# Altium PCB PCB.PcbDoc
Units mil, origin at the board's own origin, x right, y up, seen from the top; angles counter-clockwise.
Board outline 3815.03 x 1595.03 mil, 2 copper layers (Top Layer, Bottom Layer); 34 components, 24 nets, 91 pads, 348 vias.
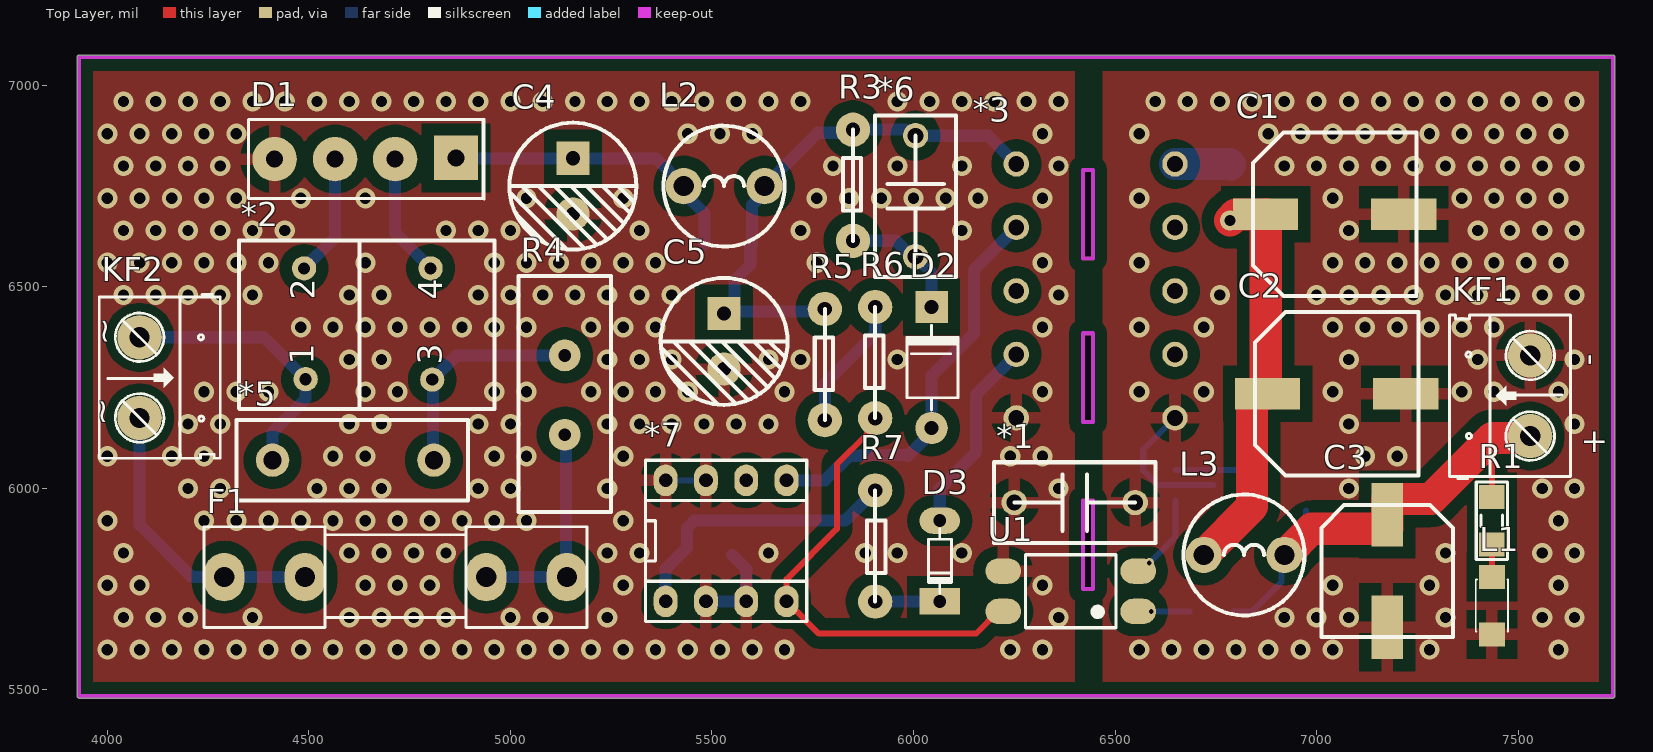
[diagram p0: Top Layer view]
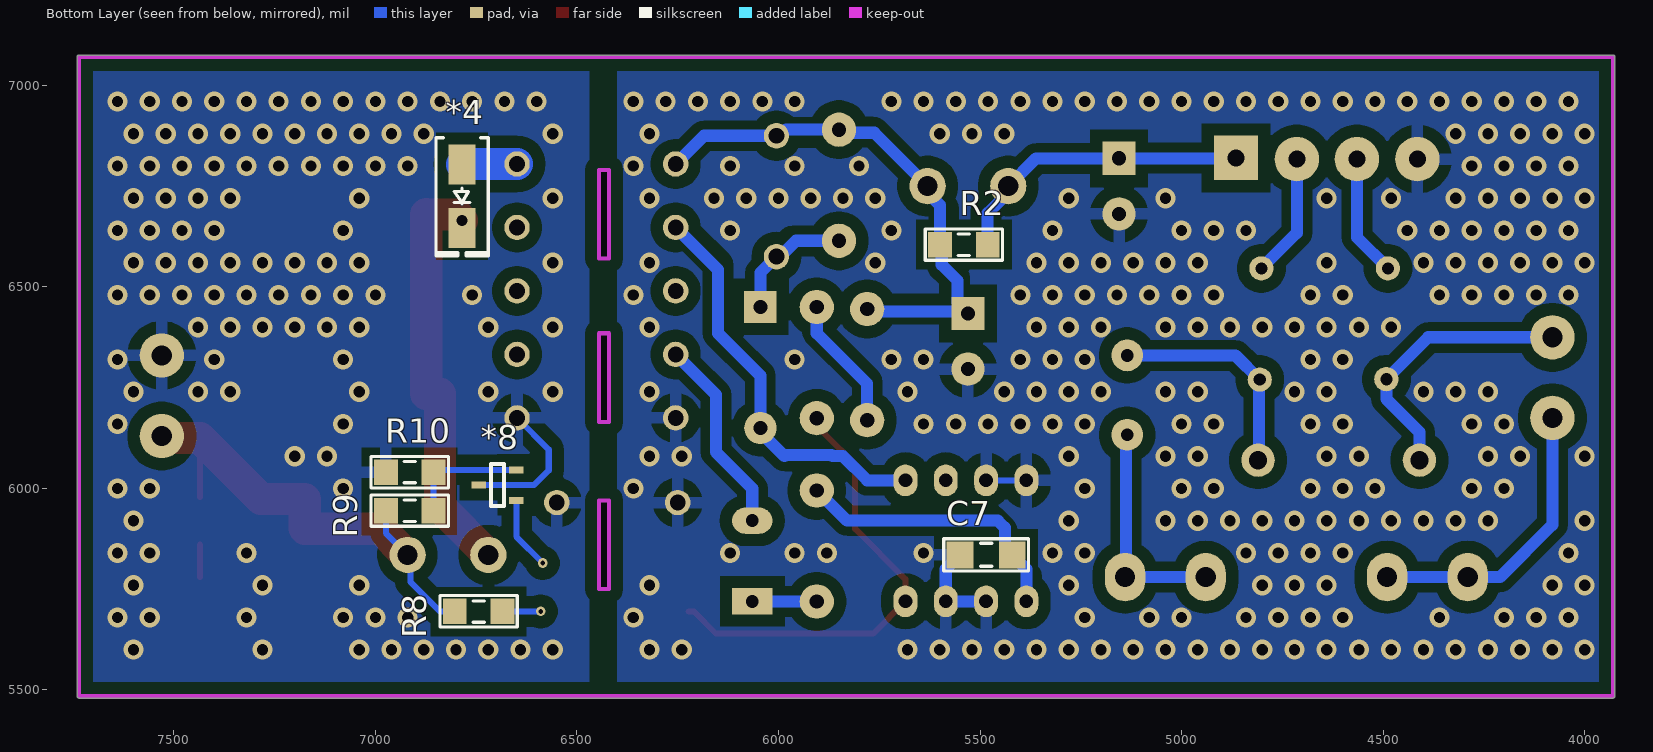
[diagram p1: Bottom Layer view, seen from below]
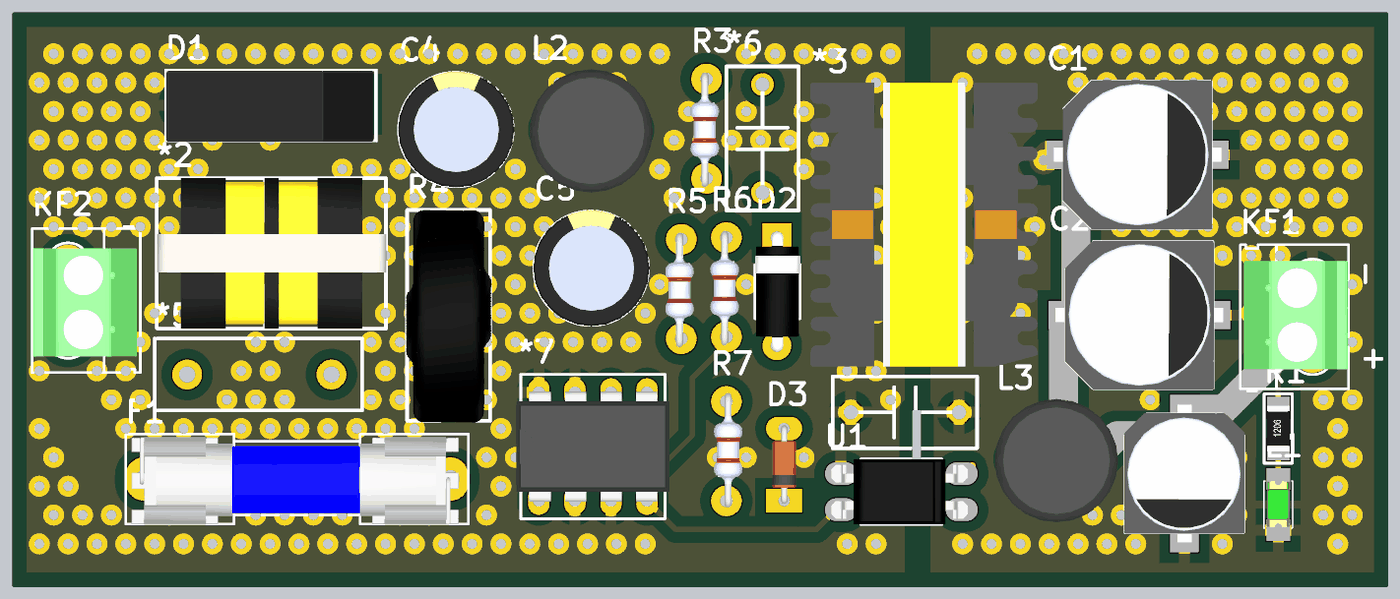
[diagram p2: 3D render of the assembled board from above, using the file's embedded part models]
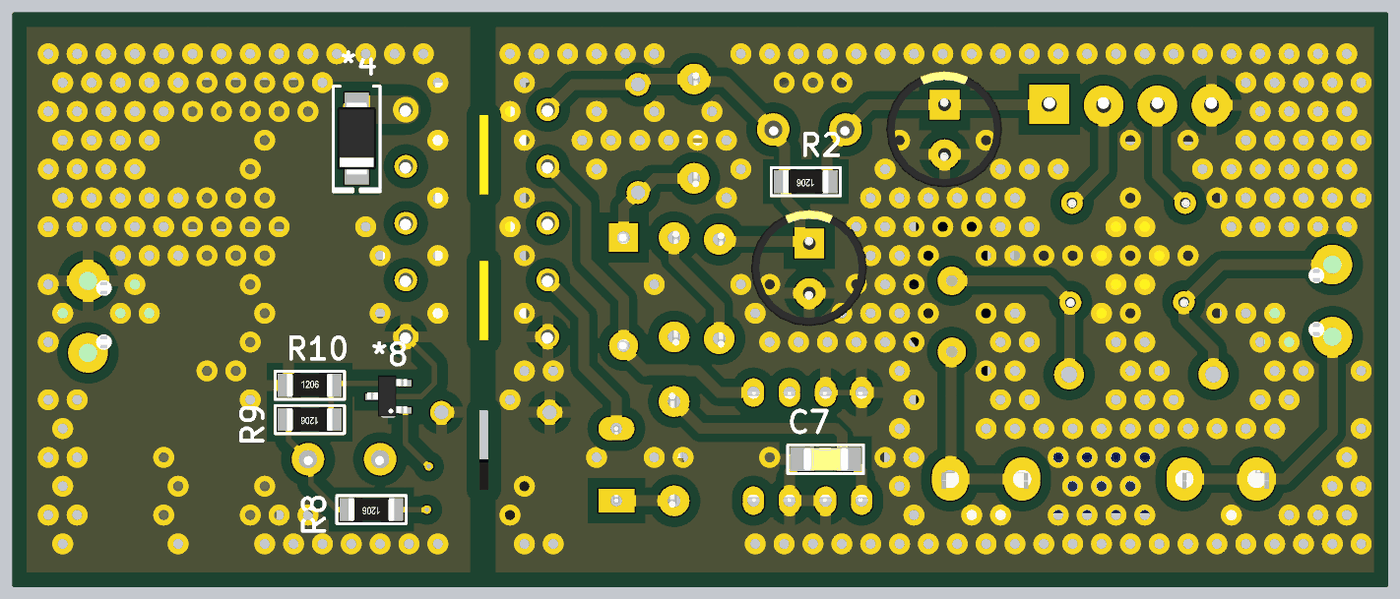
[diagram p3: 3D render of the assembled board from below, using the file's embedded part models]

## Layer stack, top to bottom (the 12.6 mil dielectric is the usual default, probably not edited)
Top Solder: solder mask 0.4, Solder Resist, Dk 3.5
Top Layer: signal copper 1.4
Dielectric 1: dielectric 12.6, FR-4, Dk 4.8
Bottom Layer: signal copper 1.4
Bottom Solder: solder mask 0.4, Solder Resist, Dk 3.5

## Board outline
3930,5479.98 cw(c3930,5485) 3924.99,5485 3924.99,7070 cw(c3930,7070) 3930,7075.02 7735,7075.02 cw(c7735,7070) 7740.02,7070 7740.02,5485 cw(c7735,5485) 7735,5479.98
cut-out: 6420,6570 6420,6790 6445,6790 6445,6570
cut-out: 6420,6165 6445,6165 6445,6385 6420,6385
cut-out: 6420,5750 6445,5750 6445,5970 6420,5970

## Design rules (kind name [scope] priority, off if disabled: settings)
Clearance [All] p1: gap=30 ignorepadtopadclearanceinfootprint=FALSE
PlaneClearance [All] p1: clearance=30
PlaneConnect [All] p1: planeconnectstyle=Relief reliefexpansion=30 reliefentries=4 reliefconductorwidth=30 reliefairgap=10
PolygonConnect [All] p1: connectstyle=Relief reliefconductorwidth=30 reliefentries=4 polygonreliefangle="90 Angle" airgapwidth=30
RoomDefinition SCH [InComponentClass('SCH')] p1: confinementstyle=ConfineIn formatcopy=TRUE lockcomponents=FALSE outline 0,0 2000,0 2000,1000 0,1000
RoutingVias [All] p1: holewidth=28 width=50 viastyle="Through Hole" minholewidth=28 minwidth=50 maxholewidth=28 maxwidth=50
SolderMaskExpansion [All] p1: expansion=4 istentingtop=FALSE
Width [All] p1: maxlimit=80 minlimit=15 preferedwidth=30
28 further rules are at their usual default settings.

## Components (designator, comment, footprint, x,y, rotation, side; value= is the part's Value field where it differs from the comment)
*1 "Tu cao ap 101/1000V" "Tu cao ap" 6650,5865 r180 top
*2 "INDUCTOR UU9.8" "INDUCTOR UU9.8" 4605,6330 r90 top
*3 "Transformer EE22" "TRANSFORMER EE22" 6908.54,6407.32 r0 top
*4 "Diode SS54 (1N5824)" "DIODE SMA" 6785,6725 r270 bottom
*5 "Tu keo vang 0.1uF" "Tu keo vang 0.1uF" 4920,6020 r0 top
*6 "Tu cao ap 2.2nF 1KV" "Tu cao ap" 6105,6975 r270 top
*7 "TNY266" DIP8 5535,5870 r0 top
*8 "TL431" "TL431 SOT-23-3" 6640,5985 r0 bottom
C1 "1000uF" "tu nhom 10 (G)" 7045,6680 r0 top
C2 "1000uF" "tu nhom 10 (G)" 7050,6235 r0 top
C3 "470uF" "tu nhom 8 (f)" 7175,5795.24 r270 top
C4 "4.7uF/400V" "tu hoa 8mm" 5155,6750 r270 top
C5 "4.7uF/400V" "tu hoa 8mm" 5530,6365 r270 top
C7 "104" "tu 1206" 5485,5835 r180 bottom
D1 "2A 600V" "DIODE CAU 2A 3A CAM" 4865,6818 r180 top
D2 "1N4973" "DIODE 1A" 6045,6100 r270 top
D3 "1N4148" "DIODE 0.5A" 6065,5820 r90 top
F1 "2A" "De Cau Chi 520 630" 4715,5780 r180 top
KF1 "5V/3A" "Con 2 KF301 5.08" 7530,6130 r90 top
KF2 "AC in" "Con 2 KF301 5.08" 4080,6375 r270 top
L1 "LED 0805" LED-1206-Green 7435,5780 r270 top
L2 "2.2mH/3A" "CUON CAM 100uH3A" 5530,6750 r0 top
L3 "10uH - 3A" "CUON CAM 100uH3A" 6820,5835 r0 top
R1 "200R" "tro smd 1206" 7435,5920 r90 top
R2 "1.2k" "tro smd 1206" 5540,6605 r0 bottom
R3 "200K" "Dien tro" 5850,6614.41 r90 top
R4 "10D-9" "tro nhiet d-9" 5135,6231.57 r270 top
R5 "2M" "Dien tro" 5780,6169.41 r90 top
R6 "2M" "Dien tro" 5905,6174.41 r90 top
R7 "10K" "Dien tro" 5905,5995 r270 top
R8 "1k" "tro smd 1206" 6744.06,5695 r0 bottom
R9 "4.7k" "tro smd 1206" 6915,5945 r0 bottom
R10 "4.7k" "tro smd 1206" 6915,6040 r180 bottom
U1 "OPTO PC817 SMD" SOP4 6390,5745 r180 top value=PC817

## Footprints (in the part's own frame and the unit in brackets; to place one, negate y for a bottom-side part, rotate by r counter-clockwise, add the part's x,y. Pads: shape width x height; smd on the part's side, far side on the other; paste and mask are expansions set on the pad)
"Con 2 KF301 5.08" [mil]
  round 110 hole 50: 1(0,0) 2(200,0)
  silkscreen extent -106,-100 300,200, body extent -45,-97 255,190, height 335
"CUON CAM 100uH3A" [mil] "100uH3A"
  round 90 hole 50: 1(-100,0) 2(100,0)
  silkscreen extent -150,-150 150,150, body extent -171,-175 171,167, height 394
"De Cau Chi 520 630" [mil] "De Fuse"
  oval 100x120 hole 50: 1(-425,0) 1(-225,0) 2(225,0) 2(425,0)
  silkscreen extent -475,-125 475,125, body extent -448,-117 459,127, height 378
"Dien tro" [mm] "c?m"
  round 2.16 hole 0.9: 1(0,0) 2(7,0)
  silkscreen extent 0,-0.51 7,0.64, body extent -0.62,-0.87 7.48,1.13, height 2.5
"DIODE 0.5A" [mil] "Diode muoi, xung"
  oval 65x100 hole 32: 1(100,0)
  rect 65x100 hole 32: 2(-100,0)
  silkscreen extent -80,-30 80,28, body extent -108,-33 108,32, height 61
"DIODE 1A" [mil] "Diode 1A"
  round 80 hole 35: 1(-50,0)
  rect 80x80 hole 35: 2(-350,0)
  silkscreen extent -305,-61 -95,65, body extent -366,-61 -34,65, height 122
"DIODE CAU 2A 3A CAM" [mil] "DIODE CAU 2A 3A CAM"
  round 110 hole 42: 1(450,1) 2(300,1) 3(151,1)
  rect 110x110 hole 42: 4(0,-2)
  silkscreen extent -70,-97 515,100, body extent -62,-95 512,102, height 650
"DIODE SMA" [mm] "SMA"
  rect 2.5x1.7 smd: 1(-2,0) 2(2,0)
  silkscreen extent -3.68,-1.65 3.75,1.65, body extent -2.6,-1.37 2.6,1.37, height 2.4
DIP8 [mm] "W.300/L.400"
  oval 1.5x2 hole 0.864: 1(-3.81,-3.81) 2(-1.27,-3.81) 3(1.27,-3.81) 4(3.81,-3.81) 5(3.81,3.81) 6(1.27,3.81) 7(-1.27,3.81) 8(-3.81,3.81)
  silkscreen extent -5.08,-5.08 5.08,5.08, body extent -5.4,-3.88 5.4,3.88, height 4.5
"INDUCTOR UU9.8" [mil]
  round 60 hole 30: 1(-59,113) 2(216,117) 3(-60,-201) 4(216,-197)
  silkscreen extent -133,-356 285,279, body extent -132,-357 286,279, height 602
LED-1206-Green [mil]
  rect 60x65 smd: 1(0,0) 2(142,0)
  silkscreen extent 6,-40 136,40, body extent 7,-31 133,32, height 43
SOP4 [mm]
  oval 2.25x1.6 smd: 1(-4.25,1.27) 2(-4.25,-1.27) 3(4.25,-1.27) 4(4.25,1.27)
  silkscreen extent -2.85,-2.3 2.85,2.3, body extent -4.67,-2.29 4.93,2.31, height 3.6
"TL431 SOT-23-3" [mm]
  rect 0.9x0.44 smd: 1(0.264,0.373) 2(0.264,-1.547) 3(2.634,-0.587)
  silkscreen extent 1.05,-1.91 1.86,0.73, body extent 0.13,-2.09 2.93,0.81, height 1.3
"TRANSFORMER EE22" [mm]
  round 1.6 hole 1: 1(-16.6,10.1) 2(-16.6,6.1) 3(-16.6,2.1) 4(-16.6,-1.9) 5(-16.6,-5.9) 6(-6.6,-5.9) 7(-6.6,-1.9) 8(-6.6,2.1) 9(-6.6,6.1) 10(-6.6,10.1)
  body extent -19.6,-8.01 -3.57,12.01, height 20.81
"tro nhiet d-9" [mm]
  round 2 hole 0.8: 1(-2.5,0) 2(2.5,0)
  silkscreen extent -7.49,-2.92 7.37,2.92, body extent -7.5,-3 7.5,3, height 23.5
"tro smd 1206" [mm]
  rect 1.5x1.6 smd: 1(-1.5,0) 2(1.5,0)
  silkscreen extent -2.44,-0.99 2.44,0.99, body extent -1.6,-0.8 1.6,0.8, height 0.6
"tu 1206" [mm]
  rect 1.7x1.7 smd: 1(-1.65,0) 2(1.65,0)
  silkscreen extent -2.67,-1.02 2.67,1.02, body extent -1.57,-0.8 1.63,0.8, height 0.94
"Tu cao ap" [mm]
  round 1.6 hole 1: 1(2.54,-2.54) 2(10.16,-2.54)
  silkscreen extent 1.27,-5.08 11.43,0
"tu hoa 8mm" [mm]
  rect 2.1x2.1 hole 0.9: 1(-1.75,0)
  round 2.1 hole 0.9: 2(1.75,0)
  silkscreen extent -4,-4 4,4, body extent -4.1,-4.07 4.1,4.13, height 13.81
"Tu keo vang 0.1uF" [mil]
  round 82.68 hole 45: 1(-510,50) 2(-110,50)
  silkscreen extent -600,-50 -25,150
"tu nhom 8 (f)" [mm]
  rect 4x2 smd: 1(-3.55,0) 2(3.55,0)
  silkscreen extent -4.15,-4.15 4.15,4.15, body extent -4.85,-4.25 4.85,4.25, height 10.5
"tu nhom 10 (G)" [mm]
  rect 4.1x2 smd: 1(-4.35,0) 2(4.35,0)
  silkscreen extent -5.15,-5.15 5.15,5.15, body extent -5.9,-5.25 5.9,5.25, height 10.5

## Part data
*1: library part "Tu cao ap 1000V"
*7: library part TNY264
C1 C2: library part "Tu Nhom 1000uF 10V", "Dán"
C3: library part "Tu Nhom 470uF 16V", "Dán"
C4 C5: library part "Tu Hoa 4.7uF 400V 8x12", "Cắm"
C7: library part "Tu 1206 104 50V 20%", "Dán"
D1: library part "Diode CAU 2A VUONG", "Cắm"
D2: library part "Diode 1N4007", "Cắm"
D3: library part "Diode 1N4148", "Cắm"
F1: library part "De Cau Chi 520 630", "5x20mm"
KF1 KF2: library part "CON 2 KF301", "Cắm"
L1: library part "LED 1206 Xanh La", "Dán"
L2 L3: library part "CUON CAM 470uH DIP", "Cắm"
R1: library part "Tro 1206 1% 200R", "Dán"
R2 R8: library part "Tro 1206 1% 1k", "Dán"
R3 R5 R6 R7: library part Resistor, "Cắm"
R4: library part "Tro Nhiet NTC 10D-9", "Cắm"
R9 R10: library part "Tro 1206 5% 4.7K", "Dán"
U1: "Single Opto"

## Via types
v1: diameter 50, hole 28, Top Layer to Bottom Layer, 346 vias
v2: diameter 23.62, hole 11.81, Top Layer to Bottom Layer, 2 vias

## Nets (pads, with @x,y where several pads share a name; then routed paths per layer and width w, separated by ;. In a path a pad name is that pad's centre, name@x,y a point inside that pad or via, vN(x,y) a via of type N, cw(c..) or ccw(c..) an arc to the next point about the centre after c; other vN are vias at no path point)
Hi_groud: *1.2 *3.5 *7.2 *7.3 *7.7 *7.8 C4.2 C5.2 C7.1 D1.1 U1.3 | length 329.5
  Bottom Layer w15: *7.8 *7.7
  Bottom Layer w30: *7.2 *7.3 5585,5799.96 C7.1
  other v1: 4000,5600 4080,5600 4160,5600 4240,5600 4320,5600 4400,5600 4480,5600 4560,5600 4640,5600 4720,5600 4800,5600 4880,5600 4960,5600 5040,5600 5120,5600 5200,5600 5280,5600 5360,5600 5440,5600 5520,5600 5600,5600 5680,5600 6240,5600 6320,5600 4040,5680 4120,5680 4200,5680 4360,5680 4600,5680 4680,5680 4760,5680 4840,5680 5000,5680 5080,5680 5240,5680 6360,5680 4000,5760 4080,5760 4640,5760 4720,5760 4800,5760 5280,5760 6320,5760 4040,5840 4600,5840 4680,5840 4760,5840 4840,5840 5240,5840 5320,5840 5640,5840 5880,5840 5960,5840 6120,5840 4000,5920 4240,5920 4320,5920 4400,5920 4480,5920 4560,5920 4640,5920 4720,5920 4800,5920 4880,5920 4960,5920 5040,5920 5280,5920 4200,6000 4280,6000 4520,6000 4600,6000 4680,6000 4920,6000 5000,6000 5240,6000 6360,6000 4000,6080 4160,6080 4240,6080 4560,6080 4640,6080 4960,6080 5040,6080 5280,6080 6240,6080 6320,6080 4200,6160 4280,6160 4600,6160 4680,6160 4920,6160 5000,6160 5240,6160 5320,6160 5400,6160 5480,6160 5560,6160 5640,6160 4240,6240 4320,6240 4400,6240 4640,6240 4720,6240 4960,6240 5040,6240 5200,6240 5280,6240 5360,6240 5440,6240 5680,6240 6320,6240 4600,6320 4680,6320 5240,6320 5320,6320 5400,6320 5640,6320 5720,6320 5960,6320 4480,6400 4560,6400 4640,6400 4720,6400 4800,6400 4880,6400 4960,6400 5040,6400 5200,6400 5280,6400 5360,6400 6320,6400 4040,6480 4120,6480 4200,6480 4280,6480 4360,6480 4600,6480 4680,6480 4920,6480 5000,6480 5080,6480 5160,6480 5240,6480 5320,6480 5400,6480 6360,6480 4000,6560 4080,6560 4160,6560 4240,6560 4320,6560 4400,6560 4640,6560 4960,6560 5040,6560 5120,6560 5200,6560 5280,6560 5360,6560 5760,6560 6320,6560 4040,6640 4120,6640 4200,6640 4280,6640 4360,6640 4440,6640 4840,6640 4920,6640 5000,6640 5320,6640 5720,6640 6120,6640 4000,6720 4080,6720 4160,6720 4240,6720 4320,6720 4480,6720 4640,6720 5040,6720 5280,6720 5760,6720 5840,6720 5920,6720 6000,6720 6080,6720 6160,6720 6320,6720 4040,6800 4120,6800 4200,6800 4280,6800 5800,6800 5960,6800 6120,6800 6360,6800 4000,6880 4080,6880 4160,6880 4240,6880 4320,6880 5440,6880 5520,6880 5600,6880 6320,6880 4040,6960 4120,6960 4200,6960 4280,6960 4360,6960 4440,6960 4520,6960 4600,6960 4680,6960 4760,6960 4840,6960 4920,6960 5000,6960 5080,6960 5160,6960 5240,6960 5320,6960 5400,6960 5480,6960 5560,6960 5640,6960 5720,6960 5960,6960 6040,6960 6120,6960 6200,6960 6280,6960 6360,6960
Lo_gnd: *1.1 *3.6 *8.3 C1.2 C2.2 C3.2 KF1.2 L1.2 R10.1 | length 351.6
  Bottom Layer w15: *3.6 6570,6096.34 6570,6045 6606.88,6008.12 *8.3
  other v1: 6560,5600 6640,5600 6720,5600 6800,5600 6880,5600 6960,5600 7040,5600 7280,5600 7600,5600 6920,5680 7000,5680 7080,5680 7320,5680 7560,5680 7640,5680 7040,5760 7280,5760 7600,5760 7320,5840 7560,5840 7640,5840 7600,5920 7080,6000 7560,6000 7640,6000 7120,6080 7200,6080 7080,6160 7640,6160 6560,6240 6720,6240 7040,6240 7360,6240 7440,6240 7600,6240 7080,6320 7400,6320 7640,6320 6560,6400 6720,6400 7040,6400 7120,6400 7200,6400 7280,6400 7360,6400 7440,6400 6760,6480 7000,6480 7080,6480 7160,6480 7240,6480 7320,6480 7400,6480 7480,6480 7560,6480 7640,6480 6560,6560 7040,6560 7120,6560 7200,6560 7280,6560 7360,6560 7440,6560 7520,6560 7600,6560 7080,6640 7400,6640 7480,6640 7560,6640 7640,6640 6560,6720 7040,6720 7360,6720 7440,6720 7520,6720 7600,6720 6920,6800 7000,6800 7080,6800 7160,6800 7240,6800 7320,6800 7400,6800 7480,6800 7560,6800 7640,6800 6560,6880 6880,6880 6960,6880 7040,6880 7120,6880 7200,6880 7280,6880 7360,6880 7440,6880 7520,6880 7600,6880 6600,6960 6680,6960 6760,6960 6840,6960 6920,6960 7000,6960 7080,6960 7160,6960 7240,6960 7320,6960 7400,6960 7480,6960 7560,6960 7640,6960
Net*2_1: *2.1 *5.1 KF2.1 | length 697.1
  Bottom Layer w15: *5.1@4405,6070 4410,6075 *5.1
  Bottom Layer w30: KF2.1 4388,6375 *2.1 4492,6222 4410,6140 *5.1@4410,6075
Net*2_2: *2.2 D1.2 | length 302.9
  Bottom Layer w30: *2.2 4565,6623 D1.2
Net*2_3: *2.3 *5.2 R4.1 | length 555.5
  Bottom Layer w30: *5.2 4808,6072 4808,6268 *2.3 4866,6330 R4.1
Net*2_4: *2.4 D1.3 | length 307.5
  Bottom Layer w30: D1.3 4714,6634 *2.4
Net*3_1: *3.1 *6.1 C5.1 L2.2 R2.2 R3.2 R5.2 | length 1561.4
  Bottom Layer w15: C5.1 5535.55,6439.45 5541.1,6445 R5.2
  Bottom Layer w30: C5.1@5535.55,6439.45 5774.45,6439.45 R5.2 ; C5.1@5541.1,6445 5556.34,6460.24 5556.34,6516.34 5595,6555 5595,6600.94 R2.2 5599.06,6702.82 5630,6733.76 L2.2 5762.48,6882.48 5842.48,6882.48 R3.2 5981.07,6890 5996.07,6875 *6.1 6184.96,6875 *3.1
Net*3_2: *3.2 *7.5 D2.1 | length 1006.3
  Bottom Layer w30: *7.5 5780,6020 5840,6080 5866.23,6080 5868.75,6082.52 5982.48,6082.52 5985,6080 6045,6140 D2.1 6045,6280 6150,6385 6150,6542.48 *3.2
Net*3_4: *3.4 D3.1 | length 491.2
  Bottom Layer w30: D3.1 6065,6000 6155,6090 6155,6232.52 *3.4
Net*3_10: *3.10 *4.1 | length 138.1
  Bottom Layer w60: *3.10 *3.10 *3.10@6650,6805
  Bottom Layer w80: *3.10 6783.78,6804.96 *4.1
Net*4_2: *4.2 C1.1 C2.1 L3.1 | length 1023
  Top Layer w80: L3.1 6840,5955 6840,6234.37 6840.63,6235 C2.1@6874.37,6235 ; v1(6785,6665) 6799.37,6679.37 6873.11,6679.37 C1.1 C2.1@6873.74,6235.63
Net*6_2: *6.2 D2.2 R3.1 | length 312.9
  Bottom Layer w30: R3.1 5956.66,6614.41 5996.07,6575 *6.2 6045,6535 D2.2
Net*7_1: *7.1 C7.2 R7.1 | length 709.4
  Bottom Layer w30: *7.1 5385,5799.96 C7.2 5438.5,5853.46 5438.5,5902.43 5456.08,5920 5830,5920 R7.1
Net*7_4: *7.4 R6.1 U1.4 | length 1139.1
  Top Layer w15: R6.1 5905,6155.46 5883.73,6134.19 5883.73,6133.73 5810,6060 5810,5900 5685,5775 *7.4 5765,5640 6155,5640 6210,5695 U1.4
Net*8_1: *8.1 U1.2 | length 182.4
  Bottom Layer w15: v2(6585,5815) 6650.39,5880.39 *8.1
Net*8_2: *8.2 R9.1 R10.2 | length 303
  Bottom Layer w15: *8.2 6850.03,6045.91 R10.2 R9.1
NetC3_1: C3.1 KF1.1 L3.2 R1.2 R8.2 R9.2 | length 1272.1
  Top Layer w15: R1.2 7435,6125
  Top Layer w80: L3.2 6922.71,5835 6987.71,5900 7174.37,5900 7175,5900.63 7175,5973.11 7175.63,5973.74 7283.74,5973.74 7435,6125 7525,6125 KF1.1
  Bottom Layer w15: R8.2@6794.06,5695 6840,5695 6912.5,5767.5 6912.5,5827.5 L3.2 6974.06,5889.06 R9.2
NetC4_1: C4.1 D1.4 L2.1 R2.1 | length 760.1
  Bottom Layer w30: D1.4 4866.1,6818.9 C4.1 5361.1,6818.9 L2.1 5430,6733.76 5480.94,6682.82 R2.1
NetD3_2: D3.2 R7.2 | length 160.2
  Bottom Layer w30: R7.2 5905.3,5719.7 6064.7,5719.7 D3.2
NetF1_1: F1.1 R4.2 | length 555.2
  Bottom Layer w30: F1.1@4940,5780 5140,5780 5137.5,5782.5 5137.5,6130.65 R4.2
NetF1_2: F1.2 KF2.2 | length 728.8
  Bottom Layer w30: KF2.2 4080,5910 4210,5780 4290,5780 F1.2@4490,5780
NetL1_1: L1.1 R1.1 | length 80.9
  Top Layer w15: L1.1 R1.1
NetR5_1: R5.1 R6.2 | length 332.4
  Bottom Layer w30: R5.1 5780,6260 5905,6385 R6.2
NetR8_1: R8.1 U1.1 | length 95
  Bottom Layer w15: v2(6590,5695) R8.1
pads on no net: *3.3 *3.7 *3.8 *3.9 *7.6

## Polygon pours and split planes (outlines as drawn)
Hi_groud on Bottom Layer "HI_GROUD_L02_P000" (solid, pour order 0): 3930,7070 3930,5485 6400,5485 6400,7070
Lo_gnd on Bottom Layer "LO_GND_L02_P002" (solid, pour order 2): 6470,7070 6470,5485 7735,5485 7735,7070
Lo_gnd on Top Layer "LO_GND_L01_P001" (solid, pour order 1): 7735,7070 6470,7070 6470,5480 7735,5480
Hi_groud on Top Layer "HI_GROUD_L01_P003" (solid, pour order 3): 3930,7070 3930,5485 6400,5485 6400,7070

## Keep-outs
Keep-Out Layer:
  lines w10: 3930,6900 3930,7070 7735,7070 ; 3930,6965 3930,5570 3930,5485 7735,5485 ; 7735,5485 7735,7070 ; 7735,5485 7735,7070 ; 6420,5750 6420,5970 6445,5970 6445,5750 6420,5750 ; 6420,6165 6420,6385 6445,6385 6445,6165 6420,6165 ; 6420,6570 6445,6570 6445,6790 6420,6790 6420,6570

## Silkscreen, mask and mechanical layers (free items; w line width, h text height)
Top Overlay:
  text "~" at 4019.98,6355 h60 r90
  text "-" at 7699.99,6305 h60 r90
  text "~" at 4014.98,6155 h60 r90
  text "+" at 7655,6090 h60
